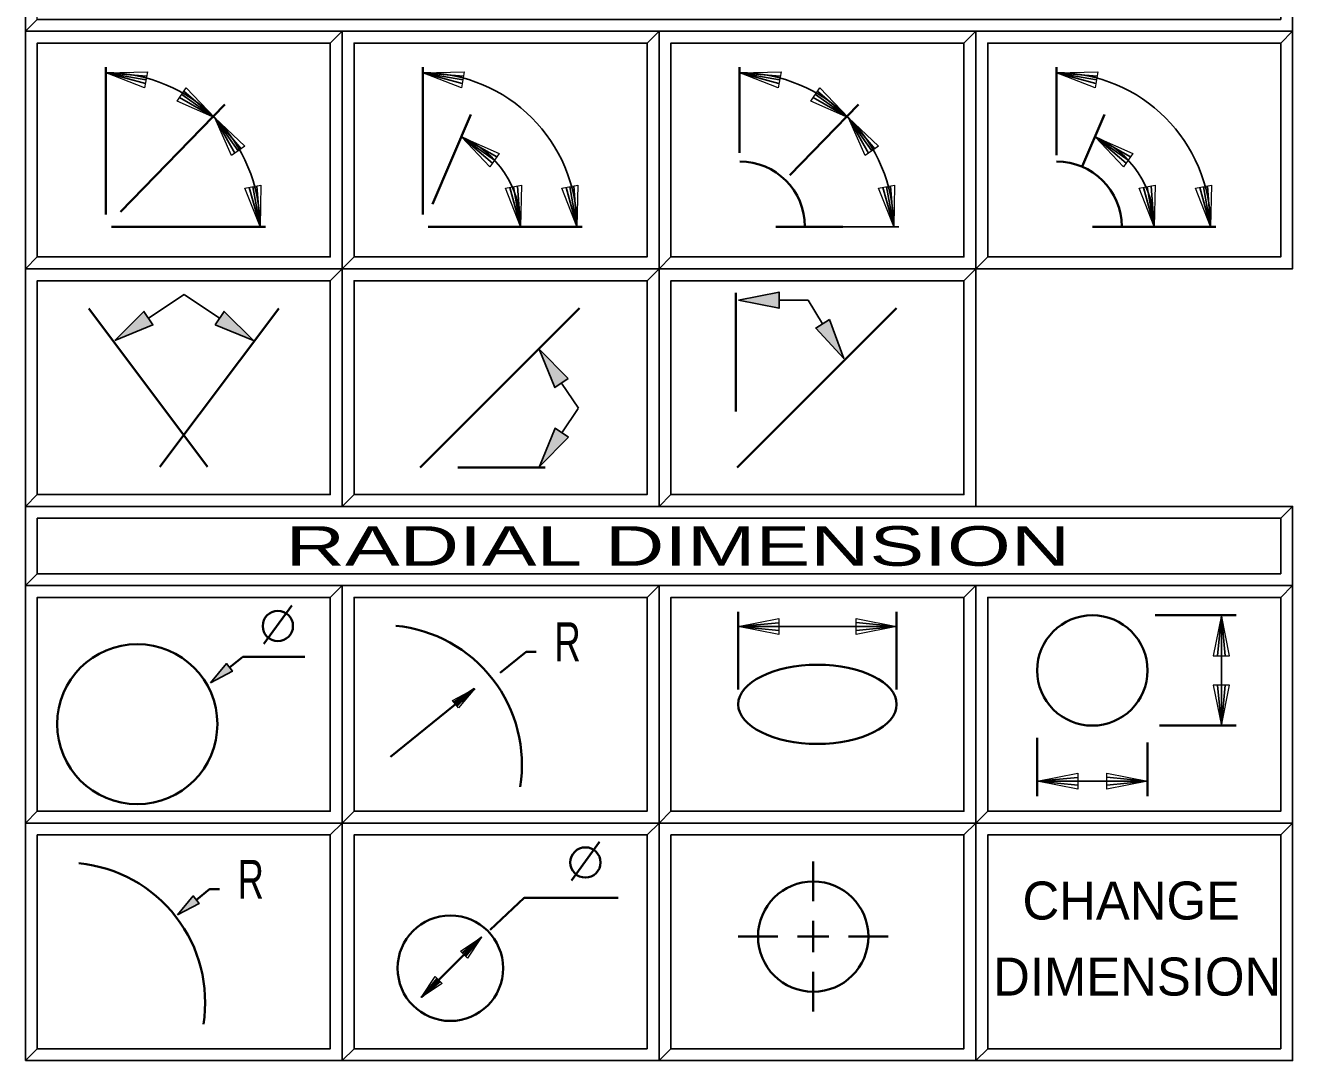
# Model space of a CAD drawing. Extents: x 95906.8 to 95923.6, y 90964.8 to 90972.8.
# Drawn here: x 95908.932 to 95910.532, y 90969.962 to 90971.269 of the extents above; entities that cross this region are included whole.
import ezdxf
from ezdxf.enums import TextEntityAlignment as Align

# ---------------------------------------------------------------- set-up
doc = ezdxf.new("R2010")
doc.units = 0
doc.header["$LTSCALE"] = 0.019
for name, color, linetype, lineweight in [('1', 7, 'Continuous', 25), ('11', 7, 'Continuous', 25), ('12', 7, 'Continuous', 25), ('17', 7, 'Continuous', 25), ('2', 7, 'Continuous', 13), ('3', 7, 'Continuous', 25), ('6', 7, 'Continuous', 35), ('7', 7, 'Continuous', 35)]:
    doc.layers.add(name, color=color, linetype=linetype, lineweight=lineweight)

msp = doc.modelspace()

# ---------------------------------------------------------------- hatches: boundary and pattern name
at = {"layer": '6'}
for points in [[(95909.8327, 90970.9222), (95909.8839, 90970.9324), (95909.8839, 90970.912)], [(95909.0451, 90970.871), (95909.082, 90970.9079), (95909.0934, 90970.8909)], [(95909.1719, 90970.8909), (95909.1833, 90970.9079), (95909.2202, 90970.871)], [(95909.9477, 90970.8976), (95909.9655, 90970.8485), (95909.9302, 90970.8869)], [(95909.6178, 90970.8232), (95909.6008, 90970.8118), (95909.5809, 90970.8601)], [(95909.6182, 90970.749), (95909.5813, 90970.7121), (95909.6012, 90970.7604)], [(95909.1661, 90970.439), (95909.1861, 90970.4631), (95909.1938, 90970.4535)], [(95909.1242, 90970.1457), (95909.1442, 90970.1698), (95909.1519, 90970.1602)]]:
    msp.add_hatch(color=256, dxfattribs=at).paths.add_polyline_path(points)

# ---------------------------------------------------------------- linework, layer by layer
at = {"layer": '1'}
for points in [[(95908.9323, 90971.2617), (95910.5323, 90971.2617), (95910.5323, 90971.3617), (95908.9323, 90971.3617)], [(95908.9323, 90970.9617), (95909.3323, 90970.9617), (95909.3323, 90971.2617), (95908.9323, 90971.2617)], [(95909.3323, 90970.9617), (95909.7323, 90970.9617), (95909.7323, 90971.2617), (95909.3323, 90971.2617)], [(95909.7323, 90970.9617), (95910.1323, 90970.9617), (95910.1323, 90971.2617), (95909.7323, 90971.2617)], [(95910.1323, 90970.9617), (95910.5323, 90970.9617), (95910.5323, 90971.2617), (95910.1323, 90971.2617)], [(95908.9323, 90970.6617), (95909.3323, 90970.6617), (95909.3323, 90970.9617), (95908.9323, 90970.9617)], [(95909.3323, 90970.6617), (95909.7323, 90970.6617), (95909.7323, 90970.9617), (95909.3323, 90970.9617)], [(95909.7323, 90970.6617), (95910.1323, 90970.6617), (95910.1323, 90970.9617), (95909.7323, 90970.9617)], [(95908.9323, 90970.5617), (95910.5323, 90970.5617), (95910.5323, 90970.6617), (95908.9323, 90970.6617)], [(95908.9323, 90970.2617), (95909.3323, 90970.2617), (95909.3323, 90970.5617), (95908.9323, 90970.5617)], [(95909.3323, 90970.2617), (95909.7323, 90970.2617), (95909.7323, 90970.5617), (95909.3323, 90970.5617)], [(95909.7323, 90970.2617), (95910.1323, 90970.2617), (95910.1323, 90970.5617), (95909.7323, 90970.5617)], [(95910.1323, 90970.2617), (95910.5323, 90970.2617), (95910.5323, 90970.5617), (95910.1323, 90970.5617)], [(95908.9323, 90969.9617), (95909.3323, 90969.9617), (95909.3323, 90970.2617), (95908.9323, 90970.2617)], [(95909.3323, 90969.9617), (95909.7323, 90969.9617), (95909.7323, 90970.2617), (95909.3323, 90970.2617)], [(95909.7323, 90969.9617), (95910.1323, 90969.9617), (95910.1323, 90970.2617), (95909.7323, 90970.2617)], [(95910.1323, 90969.9617), (95910.5323, 90969.9617), (95910.5323, 90970.2617), (95910.1323, 90970.2617)]]:
    msp.add_lwpolyline(points, close=True, dxfattribs=at)
at = {"layer": '11'}
for points in [[(95909.3473, 90970.9767), (95909.7173, 90970.9767), (95909.7173, 90971.2467), (95909.3473, 90971.2467)], [(95909.7473, 90970.9767), (95910.1173, 90970.9767), (95910.1173, 90971.2467), (95909.7473, 90971.2467)], [(95910.1473, 90970.9767), (95910.5173, 90970.9767), (95910.5173, 90971.2467), (95910.1473, 90971.2467)], [(95908.9473, 90970.6767), (95909.3173, 90970.6767), (95909.3173, 90970.9467), (95908.9473, 90970.9467)], [(95909.3473, 90970.6767), (95909.7173, 90970.6767), (95909.7173, 90970.9467), (95909.3473, 90970.9467)], [(95909.7473, 90970.6767), (95910.1173, 90970.6767), (95910.1173, 90970.9467), (95909.7473, 90970.9467)], [(95909.3473, 90970.2767), (95909.7173, 90970.2767), (95909.7173, 90970.5467), (95909.3473, 90970.5467)], [(95909.7473, 90970.2767), (95910.1173, 90970.2767), (95910.1173, 90970.5467), (95909.7473, 90970.5467)], [(95910.1473, 90970.2767), (95910.5173, 90970.2767), (95910.5173, 90970.5467), (95910.1473, 90970.5467)], [(95908.9473, 90969.9767), (95909.3173, 90969.9767), (95909.3173, 90970.2467), (95908.9473, 90970.2467)], [(95909.3473, 90969.9767), (95909.7173, 90969.9767), (95909.7173, 90970.2467), (95909.3473, 90970.2467)], [(95909.7473, 90969.9767), (95910.1173, 90969.9767), (95910.1173, 90970.2467), (95909.7473, 90970.2467)], [(95910.1473, 90969.9767), (95910.5173, 90969.9767), (95910.5173, 90970.2467), (95910.1473, 90970.2467)]]:
    msp.add_lwpolyline(points, close=True, dxfattribs=at)
at = {"layer": '12'}
for points in [[(95908.9473, 90970.9767), (95909.3173, 90970.9767), (95909.3173, 90971.2467), (95908.9473, 90971.2467)], [(95908.9473, 90970.2767), (95909.3173, 90970.2767), (95909.3173, 90970.5467), (95908.9473, 90970.5467)]]:
    msp.add_lwpolyline(points, close=True, dxfattribs=at)
at = {"layer": '17'}
msp.add_lwpolyline([(95908.9473, 90970.5767), (95910.5173, 90970.5767), (95910.5173, 90970.6467), (95908.9473, 90970.6467)], close=True, dxfattribs=at)
at = {"layer": '2'}
for points in [[(95908.9323, 90971.3617), (95908.9323, 90971.2617), (95908.9473, 90971.2767), (95908.9473, 90971.3467), (95910.5173, 90971.3467), (95910.5323, 90971.3617)], [(95908.9323, 90971.2617), (95908.9323, 90970.9617), (95908.9473, 90970.9767), (95908.9473, 90971.2467), (95909.3173, 90971.2467), (95909.3323, 90971.2617)], [(95909.3323, 90971.2617), (95909.3323, 90970.9617), (95909.3473, 90970.9767), (95909.3473, 90971.2467), (95909.7173, 90971.2467), (95909.7323, 90971.2617)], [(95909.7323, 90971.2617), (95909.7323, 90970.9617), (95909.7473, 90970.9767), (95909.7473, 90971.2467), (95910.1173, 90971.2467), (95910.1323, 90971.2617)], [(95910.1323, 90971.2617), (95910.1323, 90970.9617), (95910.1473, 90970.9767), (95910.1473, 90971.2467), (95910.5173, 90971.2467), (95910.5323, 90971.2617)], [(95908.9323, 90970.9617), (95908.9323, 90970.6617), (95908.9473, 90970.6767), (95908.9473, 90970.9467), (95909.3173, 90970.9467), (95909.3323, 90970.9617)], [(95909.3323, 90970.9617), (95909.3323, 90970.6617), (95909.3473, 90970.6767), (95909.3473, 90970.9467), (95909.7173, 90970.9467), (95909.7323, 90970.9617)], [(95909.7323, 90970.9617), (95909.7323, 90970.6617), (95909.7473, 90970.6767), (95909.7473, 90970.9467), (95910.1173, 90970.9467), (95910.1323, 90970.9617)], [(95908.9323, 90970.6617), (95908.9323, 90970.5617), (95908.9473, 90970.5767), (95908.9473, 90970.6467), (95910.5173, 90970.6467), (95910.5323, 90970.6617)], [(95908.9323, 90970.5617), (95908.9323, 90970.2617), (95908.9473, 90970.2767), (95908.9473, 90970.5467), (95909.3173, 90970.5467), (95909.3323, 90970.5617)], [(95909.3323, 90970.5617), (95909.3323, 90970.2617), (95909.3473, 90970.2767), (95909.3473, 90970.5467), (95909.7173, 90970.5467), (95909.7323, 90970.5617)], [(95909.7323, 90970.5617), (95909.7323, 90970.2617), (95909.7473, 90970.2767), (95909.7473, 90970.5467), (95910.1173, 90970.5467), (95910.1323, 90970.5617)], [(95910.1323, 90970.5617), (95910.1323, 90970.2617), (95910.1473, 90970.2767), (95910.1473, 90970.5467), (95910.5173, 90970.5467), (95910.5323, 90970.5617)], [(95908.9323, 90970.2617), (95908.9323, 90969.9617), (95908.9473, 90969.9767), (95908.9473, 90970.2467), (95909.3173, 90970.2467), (95909.3323, 90970.2617)], [(95909.3323, 90970.2617), (95909.3323, 90969.9617), (95909.3473, 90969.9767), (95909.3473, 90970.2467), (95909.7173, 90970.2467), (95909.7323, 90970.2617)], [(95909.7323, 90970.2617), (95909.7323, 90969.9617), (95909.7473, 90969.9767), (95909.7473, 90970.2467), (95910.1173, 90970.2467), (95910.1323, 90970.2617)], [(95910.1323, 90970.2617), (95910.1323, 90969.9617), (95910.1473, 90969.9767), (95910.1473, 90970.2467), (95910.5173, 90970.2467), (95910.5323, 90970.2617)]]:
    msp.add_lwpolyline(points, close=True, dxfattribs=at)
at = {"layer": '3'}
for points in [[(95908.9323, 90971.2617), (95910.5323, 90971.2617), (95910.5323, 90971.3617), (95910.5173, 90971.3467), (95910.5173, 90971.2767), (95908.9473, 90971.2767)], [(95908.9323, 90970.9617), (95909.3323, 90970.9617), (95909.3323, 90971.2617), (95909.3173, 90971.2467), (95909.3173, 90970.9767), (95908.9473, 90970.9767)], [(95909.3323, 90970.9617), (95909.7323, 90970.9617), (95909.7323, 90971.2617), (95909.7173, 90971.2467), (95909.7173, 90970.9767), (95909.3473, 90970.9767)], [(95909.7323, 90970.9617), (95910.1323, 90970.9617), (95910.1323, 90971.2617), (95910.1173, 90971.2467), (95910.1173, 90970.9767), (95909.7473, 90970.9767)], [(95910.1323, 90970.9617), (95910.5323, 90970.9617), (95910.5323, 90971.2617), (95910.5173, 90971.2467), (95910.5173, 90970.9767), (95910.1473, 90970.9767)], [(95908.9323, 90970.6617), (95909.3323, 90970.6617), (95909.3323, 90970.9617), (95909.3173, 90970.9467), (95909.3173, 90970.6767), (95908.9473, 90970.6767)], [(95909.3323, 90970.6617), (95909.7323, 90970.6617), (95909.7323, 90970.9617), (95909.7173, 90970.9467), (95909.7173, 90970.6767), (95909.3473, 90970.6767)], [(95909.7323, 90970.6617), (95910.1323, 90970.6617), (95910.1323, 90970.9617), (95910.1173, 90970.9467), (95910.1173, 90970.6767), (95909.7473, 90970.6767)], [(95908.9323, 90970.5617), (95910.5323, 90970.5617), (95910.5323, 90970.6617), (95910.5173, 90970.6467), (95910.5173, 90970.5767), (95908.9473, 90970.5767)], [(95908.9323, 90970.2617), (95909.3323, 90970.2617), (95909.3323, 90970.5617), (95909.3173, 90970.5467), (95909.3173, 90970.2767), (95908.9473, 90970.2767)], [(95909.3323, 90970.2617), (95909.7323, 90970.2617), (95909.7323, 90970.5617), (95909.7173, 90970.5467), (95909.7173, 90970.2767), (95909.3473, 90970.2767)], [(95909.7323, 90970.2617), (95910.1323, 90970.2617), (95910.1323, 90970.5617), (95910.1173, 90970.5467), (95910.1173, 90970.2767), (95909.7473, 90970.2767)], [(95910.1323, 90970.2617), (95910.5323, 90970.2617), (95910.5323, 90970.5617), (95910.5173, 90970.5467), (95910.5173, 90970.2767), (95910.1473, 90970.2767)], [(95908.9323, 90969.9617), (95909.3323, 90969.9617), (95909.3323, 90970.2617), (95909.3173, 90970.2467), (95909.3173, 90969.9767), (95908.9473, 90969.9767)], [(95909.3323, 90969.9617), (95909.7323, 90969.9617), (95909.7323, 90970.2617), (95909.7173, 90970.2467), (95909.7173, 90969.9767), (95909.3473, 90969.9767)], [(95909.7323, 90969.9617), (95910.1323, 90969.9617), (95910.1323, 90970.2617), (95910.1173, 90970.2467), (95910.1173, 90969.9767), (95909.7473, 90969.9767)], [(95910.1323, 90969.9617), (95910.5323, 90969.9617), (95910.5323, 90970.2617), (95910.5173, 90970.2467), (95910.5173, 90969.9767), (95910.1473, 90969.9767)]]:
    msp.add_lwpolyline(points, close=True, dxfattribs=at)
at = {"layer": '6'}
for p, q in [((95909.0341, 90971.0304), (95909.0341, 90971.2162)), ((95909.4341, 90971.0304), (95909.4341, 90971.2162)), ((95909.8341, 90971.1083), (95909.8341, 90971.2162)), ((95910.2341, 90971.1054), (95910.2341, 90971.2162)), ((95909.0523, 90971.0335), (95909.1842, 90971.1693)), ((95909.8975, 90971.0801), (95909.9842, 90971.1693)), ((95909.4462, 90971.0433), (95909.4949, 90971.1567)), ((95910.2666, 90971.0908), (95910.2949, 90971.1567)), ((95909.0409, 90971.0149), (95909.2353, 90971.0149)), ((95909.4409, 90971.0149), (95909.6353, 90971.0149)), ((95909.8798, 90971.0149), (95909.9643, 90971.0149)), ((95910.2798, 90971.0149), (95910.3643, 90971.0149)), ((95910.327, 90971.0149), (95910.4353, 90971.0149)), ((95909.8295, 90970.7815), (95909.8295, 90970.9315)), ((95909.4309, 90970.7109), (95909.6321, 90970.9121)), ((95909.8309, 90970.7109), (95910.0321, 90970.9121)), ((95909.1623, 90970.7117), (95909.0123, 90970.9117)), ((95909.1023, 90970.7117), (95909.2523, 90970.9117)), ((95909.4785, 90970.7109), (95909.5886, 90970.7109)), ((95909.2335, 90970.4879), (95909.2688, 90970.5366)), ((95909.8323, 90970.4305), (95909.8323, 90970.5287)), ((95910.0323, 90970.4305), (95910.0323, 90970.5287)), ((95910.3587, 90970.5242), (95910.4611, 90970.5242)), ((95909.2067, 90970.4718), (95909.1899, 90970.4583)), ((95909.2067, 90970.4718), (95909.2853, 90970.4718)), ((95909.3933, 90970.3455), (95909.4992, 90970.4312)), ((95909.4992, 90970.4312), (95909.4771, 90970.4097)), ((95910.3644, 90970.3848), (95910.4611, 90970.3848)), ((95910.2097, 90970.3694), (95910.2097, 90970.2958)), ((95910.3491, 90970.3636), (95910.3491, 90970.2958)), ((95909.6218, 90970.1893), (95909.6571, 90970.238)), ((95909.927, 90970.2131), (95909.927, 90970.1631)), ((95909.927, 90970.1381), (95909.927, 90970.0987)), ((95909.4324, 90970.0419), (95909.5079, 90970.1174)), ((95909.5079, 90970.1174), (95909.4882, 90970.0937)), ((95909.8323, 90970.1184), (95909.8823, 90970.1184)), ((95909.9073, 90970.1184), (95909.9467, 90970.1184)), ((95910.0217, 90970.1184), (95909.9717, 90970.1184)), ((95909.4324, 90970.0419), (95909.4521, 90970.0656)), ((95909.927, 90970.0237), (95909.927, 90970.0737))]:
    msp.add_line(p, q, dxfattribs=at)
at = {"layer": '6', "lineweight": 25}
for p, q in [((95909.0342, 90971.2094), (95909.0854, 90971.2052)), ((95909.4342, 90971.2094), (95909.4854, 90971.2052)), ((95909.8342, 90971.2094), (95909.8854, 90971.2052)), ((95910.2342, 90971.2094), (95910.2854, 90971.2052)), ((95909.1716, 90971.1525), (95909.1269, 90971.178)), ((95909.9716, 90971.1525), (95909.9269, 90971.178)), ((95909.1716, 90971.1525), (95909.2049, 90971.1133)), ((95909.9716, 90971.1525), (95910.0049, 90971.1133)), ((95909.4828, 90971.1285), (95909.5275, 90971.103)), ((95910.2828, 90971.1285), (95910.3275, 90971.103)), ((95909.2286, 90971.015), (95909.215, 90971.0646)), ((95909.5576, 90971.015), (95909.544, 90971.0646)), ((95909.6286, 90971.015), (95909.615, 90971.0646)), ((95910.0286, 90971.015), (95910.015, 90971.0646)), ((95910.3576, 90971.015), (95910.344, 90971.0646)), ((95910.4286, 90971.015), (95910.415, 90971.0646)), ((95909.0798, 90971.0149), (95909.1643, 90971.0149)), ((95909.4798, 90971.0149), (95909.5643, 90971.0149)), ((95909.9284, 90971.0149), (95910.0353, 90971.0149)), ((95909.1327, 90970.9294), (95909.0877, 90970.8994)), ((95909.1327, 90970.9294), (95909.1776, 90970.8994)), ((95909.9208, 90970.9222), (95909.8839, 90970.9222)), ((95909.9208, 90970.922), (95909.9389, 90970.8922)), ((95909.6305, 90970.7856), (95909.6093, 90970.8175)), ((95909.6303, 90970.7855), (95909.6097, 90970.7547)), ((95909.8323, 90970.5099), (95909.8835, 90970.5147)), ((95910.4423, 90970.3848), (95910.4423, 90970.5242)), ((95910.4423, 90970.5242), (95910.4471, 90970.473)), ((95909.8323, 90970.5099), (95910.0323, 90970.5099)), ((95910.0323, 90970.5099), (95909.9811, 90970.5051)), ((95910.4423, 90970.3848), (95910.4375, 90970.436)), ((95910.2097, 90970.3146), (95910.2609, 90970.3194)), ((95910.2097, 90970.3146), (95910.3491, 90970.3146)), ((95910.3491, 90970.3146), (95910.2979, 90970.3098))]:
    msp.add_line(p, q, dxfattribs=at)
at = {"layer": '6', "lineweight": 13}
for points in [[(95909.0828, 90971.1904), (95909.0342, 90971.2094), (95909.0864, 90971.2106)], [(95909.0828, 90971.1904), (95909.0342, 90971.2094), (95909.0864, 90971.2106)], [(95909.0828, 90971.1904), (95909.0342, 90971.2094), (95909.0864, 90971.2106)], [(95909.4828, 90971.1904), (95909.4342, 90971.2094), (95909.4864, 90971.2106)], [(95909.8828, 90971.1904), (95909.8342, 90971.2094), (95909.8864, 90971.2106)], [(95910.2828, 90971.1904), (95910.2342, 90971.2094), (95910.2864, 90971.2106)], [(95909.1716, 90971.1525), (95909.1238, 90971.1735), (95909.1355, 90971.1903)], [(95909.9716, 90971.1525), (95909.9238, 90971.1735), (95909.9355, 90971.1903)], [(95909.1926, 90971.1047), (95909.1716, 90971.1525), (95909.2094, 90971.1164)], [(95909.9926, 90971.1047), (95909.9716, 90971.1525), (95910.0094, 90971.1164)], [(95909.5189, 90971.0907), (95909.4828, 90971.1285), (95909.5306, 90971.1075)], [(95910.3189, 90971.0907), (95910.2828, 90971.1285), (95910.3306, 90971.1075)], [(95909.2286, 90971.015), (95909.2096, 90971.0636), (95909.2298, 90971.0672)], [(95909.5576, 90971.015), (95909.5386, 90971.0636), (95909.5588, 90971.0672)], [(95909.6286, 90971.015), (95909.6096, 90971.0636), (95909.6298, 90971.0672)], [(95910.0096, 90971.0636), (95910.0298, 90971.0672), (95910.0286, 90971.015)], [(95910.3588, 90971.0672), (95910.3576, 90971.015), (95910.3386, 90971.0636)], [(95910.4298, 90971.0672), (95910.4286, 90971.015), (95910.4096, 90971.0636)], [(95909.8835, 90970.5201), (95909.8835, 90970.4997), (95909.8323, 90970.5099)], [(95909.9811, 90970.4997), (95909.9811, 90970.5201), (95910.0323, 90970.5099)], [(95910.4321, 90970.473), (95910.4525, 90970.473), (95910.4423, 90970.5242)], [(95910.4525, 90970.436), (95910.4321, 90970.436), (95910.4423, 90970.3848)], [(95909.4792, 90970.4071), (95909.4715, 90970.4167), (95909.4992, 90970.4312)], [(95910.2609, 90970.3248), (95910.2609, 90970.3044), (95910.2097, 90970.3146)], [(95910.2979, 90970.3044), (95910.2979, 90970.3248), (95910.3491, 90970.3146)], [(95909.4905, 90970.0913), (95909.4818, 90970.1), (95909.5079, 90970.1174)], [(95909.4498, 90970.068), (95909.4585, 90970.0593), (95909.4324, 90970.0419)]]:
    msp.add_lwpolyline(points, close=True, dxfattribs=at)
at = {"layer": '6', "lineweight": 25}
for points in [[(95909.0846, 90971.2005), (95909.0342, 90971.2094), (95909.0838, 90971.1956)], [(95909.4846, 90971.2005), (95909.4342, 90971.2094), (95909.4838, 90971.1956)], [(95909.8846, 90971.2005), (95909.8342, 90971.2094), (95909.8838, 90971.1956)], [(95910.2846, 90971.2005), (95910.2342, 90971.2094), (95910.2838, 90971.1956)], [(95909.1297, 90971.1819), (95909.1716, 90971.1525), (95909.1325, 90971.186)], [(95909.9297, 90971.1819), (95909.9716, 90971.1525), (95909.9325, 90971.186)], [(95909.201, 90971.1106), (95909.1716, 90971.1525), (95909.1969, 90971.1077)], [(95910.001, 90971.1106), (95909.9716, 90971.1525), (95909.9969, 90971.1077)], [(95909.5247, 90971.0991), (95909.4828, 90971.1285), (95909.5219, 90971.095)], [(95910.3247, 90971.0991), (95910.2828, 90971.1285), (95910.3219, 90971.095)], [(95909.2197, 90971.0654), (95909.2286, 90971.015), (95909.2246, 90971.0663)], [(95909.5487, 90971.0654), (95909.5576, 90971.015), (95909.5536, 90971.0663)], [(95909.6197, 90971.0654), (95909.6286, 90971.015), (95909.6246, 90971.0663)], [(95910.0197, 90971.0654), (95910.0286, 90971.015), (95910.0246, 90971.0663)], [(95910.3487, 90971.0654), (95910.3576, 90971.015), (95910.3536, 90971.0663)], [(95910.4197, 90971.0654), (95910.4286, 90971.015), (95910.4246, 90971.0663)], [(95909.9811, 90970.5099), (95910.0323, 90970.5099), (95909.9811, 90970.5149)], [(95910.4423, 90970.473), (95910.4423, 90970.5242), (95910.4373, 90970.473)], [(95909.8835, 90970.5099), (95909.8323, 90970.5099), (95909.8835, 90970.5049)], [(95910.4423, 90970.436), (95910.4423, 90970.3848), (95910.4473, 90970.436)], [(95910.2609, 90970.3146), (95910.2097, 90970.3146), (95910.2609, 90970.3096)], [(95910.2979, 90970.3146), (95910.3491, 90970.3146), (95910.2979, 90970.3196)]]:
    msp.add_lwpolyline(points, dxfattribs=at)
for points in [[(95909.8327, 90970.9222), (95909.8839, 90970.9324), (95909.8839, 90970.912)], [(95909.0451, 90970.871), (95909.082, 90970.9079), (95909.0934, 90970.8909)], [(95909.1719, 90970.8909), (95909.1833, 90970.9079), (95909.2202, 90970.871)], [(95909.9477, 90970.8976), (95909.9655, 90970.8485), (95909.9302, 90970.8869)], [(95909.6178, 90970.8232), (95909.6008, 90970.8118), (95909.5809, 90970.8601)], [(95909.6182, 90970.749), (95909.5813, 90970.7121), (95909.6012, 90970.7604)], [(95909.1661, 90970.439), (95909.1861, 90970.4631), (95909.1938, 90970.4535)], [(95909.1242, 90970.1457), (95909.1442, 90970.1698), (95909.1519, 90970.1602)]]:
    msp.add_lwpolyline(points, close=True, dxfattribs=at)
at = {"layer": '6'}
for points in [[(95909.5319, 90970.4513), (95909.5647, 90970.4782), (95909.5773, 90970.4782)], [(95909.4753, 90970.4119), (95909.4992, 90970.4312), (95909.4734, 90970.4142)], [(95909.1482, 90970.1647), (95909.1647, 90970.1782), (95909.1773, 90970.1782)], [(95909.5193, 90970.1271), (95909.5621, 90970.1674), (95909.6806, 90970.1674)], [(95909.4862, 90970.0957), (95909.5079, 90970.1174), (95909.4841, 90970.0978)], [(95909.4541, 90970.0636), (95909.4324, 90970.0419), (95909.4562, 90970.0615)]]:
    msp.add_lwpolyline(points, dxfattribs=at)
for centre, radius in [((95909.2511, 90970.5106), 0.0191), ((95910.2794, 90970.4545), 0.0697), ((95909.0736, 90970.3867), 0.1011), ((95909.6394, 90970.212), 0.0191), ((95909.927, 90970.1184), 0.0697), ((95909.4689, 90970.0784), 0.0666)]:
    msp.add_circle(centre, radius, dxfattribs=at)
at = {"layer": '6', "lineweight": 25}
for centre, radius, end in [((95909.0342, 90971.015), 0.1944, 90), ((95909.4342, 90971.015), 0.1944, 90), ((95909.8342, 90971.015), 0.1944, 90), ((95910.2342, 90971.015), 0.1944, 90), ((95909.4342, 90971.015), 0.1234, 66.8084), ((95910.2342, 90971.015), 0.1234, 66.8084)]:
    msp.add_arc(centre, radius, 0, end, dxfattribs=at)
at = {"layer": '6'}
for centre, radius, start, end in [((95909.8342, 90971.015), 0.0823, 0, 90), ((95910.2342, 90971.015), 0.0823, 0, 90), ((95909.3829, 90970.3354), 0.1764, 350.954, 84.4361), ((95908.9829, 90970.0354), 0.1764, 350.954, 84.4361)]:
    msp.add_arc(centre, radius, start, end, dxfattribs=at)
msp.add_ellipse((95909.9323, 90970.4117), major_axis=(-0.1, 0), ratio=0.5, dxfattribs=at)

# ---------------------------------------------------------------- texts
at = {"layer": '6', "width": 0.7}
for p in [(95909.6169, 90970.4662), (95909.2169, 90970.1662)]:
    msp.add_text('R', height=0.0491, dxfattribs=at).set_placement(p, align=Align.CENTER)
at = {"layer": '6'}
for s, p in [('CHANGE', (95910.3285, 90970.1399)), ('DIMENSION', (95910.336, 90970.0439))]:
    msp.add_text(s, height=0.048, dxfattribs=at).set_placement(p, align=Align.CENTER)
at = {"layer": '7', "width": 1.55}
msp.add_text('    RADIAL DIMENSION   ', height=0.04999, dxfattribs=at).set_placement((95909.7418, 90970.5867), align=Align.CENTER)

doc.saveas('drawing.dxf')
